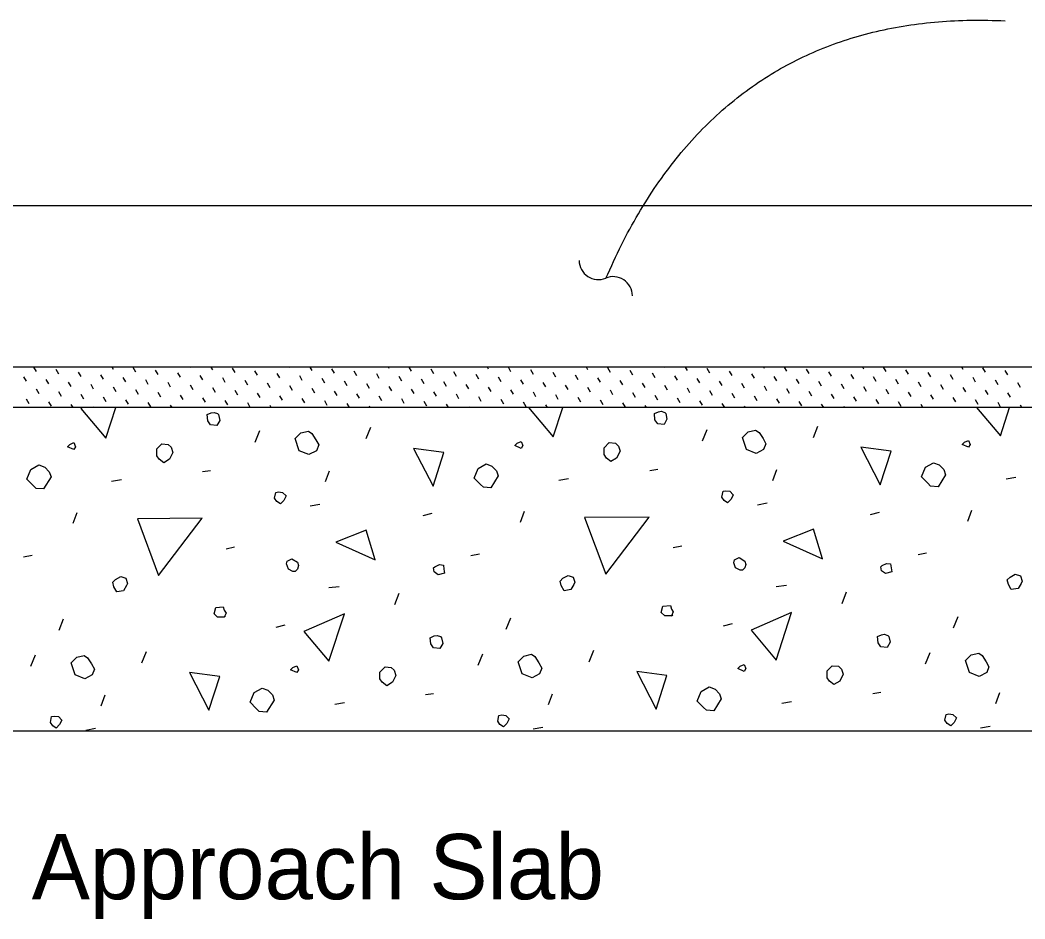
# Model space of a CAD drawing. Extents: x 0 to 40.8, y 1 to 28.
# Drawn here: x 1.979 to 5.085, y 9.449 to 12.227 of the extents above; entities that cross this region are included whole.
import ezdxf

# ---------------------------------------------------------------- set-up
doc = ezdxf.new("R2010")
doc.units = 0
for name, color, linetype in [('Dimension', 7, 'Continuous'), ('Miscellaneous', 7, 'Continuous'), ('TrafBarrierConc', 7, 'Continuous')]:
    doc.layers.add(name, color=color, linetype=linetype)

msp = doc.modelspace()

# ---------------------------------------------------------------- linework, layer by layer
at = {"layer": 'Dimension'}
for centre, start, end in [((3.7662, 11.4849), 180.7649, 292.4921), ((3.8118, 11.3748), 0.7649, 112.4921)]:
    msp.add_arc(centre, 0.0596, start, end, dxfattribs=at)
msp.add_open_spline([(3.7897, 11.4295), (4.1501, 12.2652), (5.0233, 12.2254)], degree=2, dxfattribs=at)
at = {"layer": 'Miscellaneous'}
for p, q in [((2.0293, 11.1415), (2.0218, 11.1545)), ((2.2674, 11.1477), (2.2634, 11.1545)), ((2.3365, 11.1396), (2.3284, 11.1536)), ((2.5054, 11.154), (2.5051, 11.1545)), ((2.5746, 11.1459), (2.5695, 11.1545)), ((2.6437, 11.1378), (2.6356, 11.1517)), ((2.8126, 11.1521), (2.8112, 11.1545)), ((2.8817, 11.144), (2.8756, 11.1545)), ((2.9509, 11.1359), (2.9428, 11.1499)), ((3.1198, 11.1502), (3.1173, 11.1545)), ((3.1889, 11.1421), (3.1817, 11.1545)), ((3.4269, 11.1483), (3.4234, 11.1545)), ((3.4961, 11.1402), (3.488, 11.1542)), ((3.7341, 11.1464), (3.7295, 11.1545)), ((3.8033, 11.1383), (3.7952, 11.1523)), ((3.9722, 11.1527), (3.9711, 11.1545)), ((4.0413, 11.1446), (4.0356, 11.1545)), ((4.1105, 11.1365), (4.1024, 11.1505)), ((4.2793, 11.1508), (4.2772, 11.1545)), ((4.3485, 11.1427), (4.3417, 11.1545)), ((4.5865, 11.1489), (4.5833, 11.1545)), ((4.6557, 11.1408), (4.6478, 11.1545)), ((4.8937, 11.147), (4.8894, 11.1545)), ((4.9629, 11.1389), (4.9548, 11.1529)), ((1.9988, 11.111), (1.9907, 11.125)), ((2.0985, 11.1334), (2.0904, 11.1474)), ((2.1677, 11.1253), (2.1596, 11.1393)), ((2.2368, 11.1172), (2.2287, 11.1312)), ((2.306, 11.1091), (2.2979, 11.1231)), ((2.4057, 11.1315), (2.3976, 11.1455)), ((2.4749, 11.1234), (2.4668, 11.1374)), ((2.544, 11.1153), (2.5359, 11.1293)), ((2.6132, 11.1072), (2.6051, 11.1212)), ((2.7129, 11.1296), (2.7048, 11.1436)), ((2.782, 11.1215), (2.7739, 11.1355)), ((2.8512, 11.1134), (2.8431, 11.1274)), ((2.9204, 11.1053), (2.9123, 11.1193)), ((3.0201, 11.1278), (3.012, 11.1418)), ((3.0892, 11.1197), (3.0811, 11.1337)), ((3.1584, 11.1116), (3.1503, 11.1256)), ((3.2581, 11.134), (3.25, 11.148)), ((3.3273, 11.1259), (3.3192, 11.1399)), ((3.3964, 11.1178), (3.3883, 11.1318)), ((3.4656, 11.1097), (3.4575, 11.1237)), ((3.5653, 11.1321), (3.5572, 11.1461)), ((3.6344, 11.124), (3.6263, 11.138)), ((3.7036, 11.1159), (3.6955, 11.1299)), ((3.7728, 11.1078), (3.7647, 11.1218)), ((3.8725, 11.1302), (3.8644, 11.1442)), ((3.9416, 11.1221), (3.9335, 11.1361)), ((4.0108, 11.114), (4.0027, 11.128)), ((4.08, 11.1059), (4.0719, 11.1199)), ((4.1797, 11.1284), (4.1715, 11.1424)), ((4.2488, 11.1203), (4.2407, 11.1343)), ((4.318, 11.1122), (4.3099, 11.1261)), ((4.4177, 11.1346), (4.4096, 11.1486)), ((4.4868, 11.1265), (4.4787, 11.1405)), ((4.556, 11.1184), (4.5479, 11.1324)), ((4.6252, 11.1103), (4.6171, 11.1243)), ((4.7249, 11.1327), (4.7168, 11.1467)), ((4.794, 11.1246), (4.7859, 11.1386)), ((4.8632, 11.1165), (4.8551, 11.1305)), ((4.9324, 11.1084), (4.9242, 11.1224)), ((5.032, 11.1308), (5.0239, 11.1448)), ((2.068, 11.1029), (2.0599, 11.1169)), ((2.1371, 11.0948), (2.129, 11.1088)), ((2.2063, 11.0867), (2.1982, 11.1007)), ((2.2755, 11.0786), (2.2674, 11.0926)), ((2.3752, 11.101), (2.3671, 11.115)), ((2.4443, 11.0929), (2.4362, 11.1069)), ((2.5135, 11.0848), (2.5054, 11.0988)), ((2.5827, 11.0767), (2.5746, 11.0907)), ((2.6824, 11.0991), (2.6742, 11.1131)), ((2.7515, 11.091), (2.7434, 11.105)), ((2.8207, 11.0829), (2.8126, 11.0969)), ((2.8898, 11.0748), (2.8817, 11.0888)), ((2.9895, 11.0972), (2.9814, 11.1112)), ((3.0587, 11.0891), (3.0506, 11.1031)), ((3.1279, 11.081), (3.1198, 11.095)), ((3.2276, 11.1035), (3.2195, 11.1175)), ((3.2967, 11.0954), (3.2886, 11.1094)), ((3.3659, 11.0873), (3.3578, 11.1013)), ((3.4351, 11.0792), (3.4269, 11.0932)), ((3.5347, 11.1016), (3.5266, 11.1156)), ((3.6039, 11.0935), (3.5958, 11.1075)), ((3.6731, 11.0854), (3.665, 11.0994)), ((3.7422, 11.0773), (3.7341, 11.0913)), ((3.8419, 11.0997), (3.8338, 11.1137)), ((3.9111, 11.0916), (3.903, 11.1056)), ((3.9803, 11.0835), (3.9722, 11.0975)), ((4.0494, 11.0754), (4.0413, 11.0894)), ((4.1491, 11.0978), (4.141, 11.1118)), ((4.2183, 11.0897), (4.2102, 11.1037)), ((4.2874, 11.0816), (4.2793, 11.0956)), ((4.3566, 11.0735), (4.3485, 11.0875)), ((4.3871, 11.1041), (4.379, 11.118)), ((4.4563, 11.096), (4.4482, 11.1099)), ((4.5255, 11.0878), (4.5174, 11.1018)), ((4.5946, 11.0797), (4.5865, 11.0937)), ((4.6943, 11.1022), (4.6862, 11.1162)), ((4.7635, 11.0941), (4.7554, 11.1081)), ((4.8327, 11.086), (4.8246, 11.1)), ((4.9018, 11.0779), (4.8937, 11.0919)), ((5.0015, 11.1003), (4.9934, 11.1143)), ((5.0707, 11.0922), (5.0626, 11.1062)), ((2.0374, 11.0723), (2.0293, 11.0863)), ((2.1066, 11.0642), (2.0985, 11.0782)), ((2.1758, 11.0561), (2.1677, 11.0701)), ((2.2449, 11.048), (2.2368, 11.062)), ((2.3446, 11.0705), (2.3365, 11.0845)), ((2.4138, 11.0624), (2.4057, 11.0764)), ((2.483, 11.0543), (2.4749, 11.0683)), ((2.5521, 11.0462), (2.544, 11.0602)), ((2.6518, 11.0686), (2.6437, 11.0826)), ((2.721, 11.0605), (2.7129, 11.0745)), ((2.7901, 11.0524), (2.782, 11.0664)), ((2.8593, 11.0443), (2.8512, 11.0583)), ((2.959, 11.0667), (2.9509, 11.0807)), ((3.0282, 11.0586), (3.0201, 11.0726)), ((3.0973, 11.0505), (3.0892, 11.0645)), ((3.1665, 11.0424), (3.1584, 11.0564)), ((3.197, 11.0729), (3.1889, 11.0869)), ((3.2662, 11.0648), (3.2581, 11.0788)), ((3.3354, 11.0567), (3.3273, 11.0707)), ((3.4045, 11.0486), (3.3964, 11.0626)), ((3.5042, 11.0711), (3.4961, 11.085)), ((3.5734, 11.063), (3.5653, 11.0769)), ((3.6425, 11.0548), (3.6344, 11.0688)), ((3.7117, 11.0467), (3.7036, 11.0607)), ((3.8114, 11.0692), (3.8033, 11.0832)), ((3.8806, 11.0611), (3.8725, 11.0751)), ((3.9497, 11.053), (3.9416, 11.067)), ((4.0189, 11.0449), (4.0108, 11.0589)), ((4.1186, 11.0673), (4.1105, 11.0813)), ((4.1878, 11.0592), (4.1797, 11.0732)), ((4.2569, 11.0511), (4.2488, 11.0651)), ((4.3261, 11.043), (4.318, 11.057)), ((4.4258, 11.0654), (4.4177, 11.0794)), ((4.4949, 11.0573), (4.4868, 11.0713)), ((4.5641, 11.0492), (4.556, 11.0632)), ((4.6638, 11.0716), (4.6557, 11.0856)), ((4.733, 11.0635), (4.7249, 11.0775)), ((4.8021, 11.0554), (4.794, 11.0694)), ((4.8713, 11.0473), (4.8632, 11.0613)), ((4.971, 11.0698), (4.9629, 11.0838)), ((5.0401, 11.0617), (5.032, 11.0757)), ((2.0069, 11.0418), (1.9988, 11.0558)), ((2.0761, 11.0337), (2.068, 11.0477)), ((2.143, 11.0295), (2.1371, 11.0396)), ((2.2075, 11.0295), (2.2063, 11.0315)), ((2.3141, 11.0399), (2.306, 11.0539)), ((2.3833, 11.0318), (2.3752, 11.0458)), ((2.4491, 11.0295), (2.4443, 11.0377)), ((2.5136, 11.0295), (2.5135, 11.0296)), ((2.6213, 11.0381), (2.6132, 11.0521)), ((2.6905, 11.03), (2.6824, 11.0439)), ((2.7552, 11.0295), (2.7515, 11.0358)), ((2.9285, 11.0362), (2.9204, 11.0502)), ((2.9968, 11.0295), (2.9895, 11.0421)), ((3.0613, 11.0295), (3.0587, 11.034)), ((3.2357, 11.0343), (3.2276, 11.0483)), ((3.3029, 11.0295), (3.2967, 11.0402)), ((3.3674, 11.0295), (3.3659, 11.0321)), ((3.4737, 11.0405), (3.4656, 11.0545)), ((3.5428, 11.0324), (3.5347, 11.0464)), ((3.609, 11.0295), (3.6039, 11.0383)), ((3.6735, 11.0295), (3.6731, 11.0302)), ((3.7809, 11.0386), (3.7728, 11.0526)), ((3.85, 11.0305), (3.8419, 11.0445)), ((3.9151, 11.0295), (3.9111, 11.0364)), ((4.0881, 11.0368), (4.08, 11.0508)), ((4.1567, 11.0295), (4.1491, 11.0427)), ((4.2212, 11.0295), (4.2183, 11.0346)), ((4.3952, 11.0349), (4.3871, 11.0489)), ((4.4628, 11.0295), (4.4563, 11.0408)), ((4.5273, 11.0295), (4.5255, 11.0327)), ((4.6333, 11.0411), (4.6252, 11.0551)), ((4.7024, 11.033), (4.6943, 11.047)), ((4.7689, 11.0295), (4.7635, 11.0389)), ((4.8334, 11.0295), (4.8327, 11.0308)), ((4.9405, 11.0392), (4.9324, 11.0532)), ((5.0096, 11.0311), (5.0015, 11.0451)), ((5.075, 11.0295), (5.0707, 11.037)), ((3.0485, 10.9337), (3.0626, 10.969)), ((4.4309, 10.9372), (4.445, 10.9725)), ((2.7056, 10.923), (2.7197, 10.9584)), ((4.088, 10.9266), (4.1021, 10.9619)), ((2.5677, 10.8347), (2.5429, 10.8311)), ((2.923, 10.8011), (2.9354, 10.8347)), ((3.6743, 10.8099), (3.6442, 10.8046)), ((3.9501, 10.8382), (3.9253, 10.8347)), ((4.3054, 10.8046), (4.3178, 10.8382)), ((5.0567, 10.8134), (5.0266, 10.8081)), ((2.2919, 10.8064), (2.2618, 10.8011)), ((2.9053, 10.7304), (2.8753, 10.7251)), ((4.2877, 10.7339), (4.2577, 10.7286)), ((2.1434, 10.672), (2.1558, 10.7056)), ((3.2518, 10.7021), (3.2235, 10.695)), ((3.5258, 10.6756), (3.5382, 10.7091)), ((4.6342, 10.7056), (4.6059, 10.6985)), ((4.9082, 10.6791), (4.9206, 10.7127)), ((2.6419, 10.5978), (2.6154, 10.5925)), ((4.0243, 10.6013), (3.9978, 10.596)), ((2.0161, 10.573), (1.9896, 10.5677)), ((3.3985, 10.5766), (3.372, 10.5713)), ((4.7809, 10.5801), (4.7544, 10.5748)), ((2.9654, 10.4758), (2.9336, 10.4723)), ((4.3478, 10.4793), (4.316, 10.4758)), ((3.1369, 10.421), (3.151, 10.4564)), ((4.5193, 10.4245), (4.5334, 10.4599)), ((2.0992, 10.3415), (2.1134, 10.3768)), ((3.4816, 10.345), (3.4958, 10.3803)), ((4.864, 10.3485), (4.8781, 10.3839)), ((2.7975, 10.3574), (2.7692, 10.3503)), ((4.1799, 10.3609), (4.1516, 10.3538)), ((2.0126, 10.2301), (2.0267, 10.2654)), ((2.3555, 10.2407), (2.3697, 10.276)), ((3.395, 10.2336), (3.4091, 10.269)), ((3.7379, 10.2442), (3.7521, 10.2796)), ((4.7774, 10.2372), (4.7915, 10.2725)), ((2.23, 10.1081), (2.2424, 10.1417)), ((3.2571, 10.1452), (3.2324, 10.1417)), ((3.6124, 10.1116), (3.6248, 10.1452)), ((4.6395, 10.1488), (4.6147, 10.1452)), ((4.9948, 10.1152), (5.0072, 10.1488)), ((2.9813, 10.1169), (2.9513, 10.1116)), ((4.3637, 10.1205), (4.3337, 10.1152)), ((2.2124, 10.0374), (2.1823, 10.0321)), ((3.5947, 10.0409), (3.5647, 10.0356)), ((4.9771, 10.0445), (4.9471, 10.0392))]:
    msp.add_line(p, q, dxfattribs=at)
for points in [[(2.1714, 11.0295), (2.1664, 11.0273), (2.2442, 10.9354)], [(2.2442, 10.9354), (2.2748, 11.0295)], [(3.5499, 11.0295), (3.6266, 10.939)], [(3.6266, 10.939), (3.656, 11.0295)], [(4.9353, 11.0295), (5.009, 10.9425)], [(5.009, 10.9425), (5.0373, 11.0295)], [(2.596, 10.9902), (2.5871, 10.9743), (2.5677, 10.9761), (2.5588, 10.9885), (2.5571, 11.0079), (2.5694, 11.0132), (2.5783, 11.015), (2.5889, 11.0114), (2.5924, 11.0079), (2.596, 10.9902)], [(3.9784, 10.9938), (3.9695, 10.9779), (3.9501, 10.9796), (3.9412, 10.992), (3.9395, 11.0114), (3.9518, 11.0167), (3.9607, 11.0185), (3.9713, 11.015), (3.9748, 11.0114), (3.9784, 10.9938)], [(2.8947, 10.8965), (2.8717, 10.8842), (2.8417, 10.8965), (2.8293, 10.9337), (2.847, 10.9513), (2.87, 10.9566), (2.8806, 10.9496), (2.8929, 10.9301), (2.9018, 10.9142), (2.8947, 10.8965)], [(4.2771, 10.9001), (4.2541, 10.8877), (4.2241, 10.9001), (4.2117, 10.9372), (4.2294, 10.9549), (4.2524, 10.9602), (4.263, 10.9531), (4.2753, 10.9337), (4.2842, 10.9177), (4.2771, 10.9001)], [(2.1452, 10.9001), (2.1257, 10.9089), (2.1328, 10.916), (2.1452, 10.9213), (2.1505, 10.9089), (2.1452, 10.9001)], [(2.451, 10.8912), (2.4404, 10.87), (2.4227, 10.8594), (2.4086, 10.87), (2.4015, 10.8806), (2.4015, 10.9018), (2.4174, 10.9177), (2.4369, 10.916), (2.4457, 10.9071), (2.451, 10.8912)], [(3.2553, 10.7869), (3.2889, 10.8912), (3.1952, 10.9036), (3.2553, 10.7869)], [(3.5276, 10.9036), (3.5081, 10.9124), (3.5152, 10.9195), (3.5276, 10.9248), (3.5329, 10.9124), (3.5276, 10.9036)], [(3.8334, 10.8948), (3.8228, 10.8736), (3.8051, 10.8629), (3.791, 10.8736), (3.7839, 10.8842), (3.7839, 10.9054), (3.7998, 10.9213), (3.8193, 10.9195), (3.8281, 10.9107), (3.8334, 10.8948)], [(4.6377, 10.7905), (4.6713, 10.8948), (4.5776, 10.9071), (4.6377, 10.7905)], [(4.91, 10.9071), (4.8905, 10.916), (4.8976, 10.923), (4.91, 10.9284), (4.9153, 10.916), (4.91, 10.9071)], [(2.0745, 10.8152), (2.0515, 10.7781), (2.0285, 10.7799), (2.0197, 10.7887), (2.0002, 10.8081), (2.0126, 10.8382), (2.0373, 10.8523), (2.055, 10.8453), (2.0692, 10.8311), (2.0745, 10.8152)], [(3.4569, 10.8188), (3.4339, 10.7816), (3.4109, 10.7834), (3.4021, 10.7922), (3.3826, 10.8117), (3.395, 10.8417), (3.4197, 10.8559), (3.4374, 10.8488), (3.4516, 10.8347), (3.4569, 10.8188)], [(4.8393, 10.8223), (4.8163, 10.7852), (4.7933, 10.7869), (4.7845, 10.7958), (4.765, 10.8152), (4.7774, 10.8453), (4.8021, 10.8594), (4.8198, 10.8523), (4.834, 10.8382), (4.8393, 10.8223)], [(2.7939, 10.7427), (2.7833, 10.7321), (2.7727, 10.7392), (2.7657, 10.7498), (2.7692, 10.7675), (2.778, 10.7693), (2.7904, 10.7675), (2.801, 10.7569), (2.7939, 10.7427)], [(4.1763, 10.7463), (4.1657, 10.7357), (4.1551, 10.7427), (4.1481, 10.7533), (4.1516, 10.771), (4.1604, 10.7728), (4.1728, 10.771), (4.1834, 10.7604), (4.1763, 10.7463)], [(2.4068, 10.5112), (2.5412, 10.6879), (2.3414, 10.6862), (2.4068, 10.5112)], [(3.7892, 10.5147), (3.9236, 10.6915), (3.7238, 10.6897), (3.7892, 10.5147)], [(4.4592, 10.5624), (4.4309, 10.6543), (4.3372, 10.6172), (4.4592, 10.5624)], [(3.0768, 10.5589), (3.0485, 10.6508), (2.9548, 10.6137), (3.0768, 10.5589)], [(2.8293, 10.5235), (2.8222, 10.5235), (2.8081, 10.5306), (2.8028, 10.5465), (2.8046, 10.5554), (2.8187, 10.5624), (2.8364, 10.5518), (2.8399, 10.5412), (2.8364, 10.5306), (2.8293, 10.5235)], [(4.2117, 10.5271), (4.2046, 10.5271), (4.1905, 10.5341), (4.1852, 10.5501), (4.1869, 10.5589), (4.2011, 10.566), (4.2188, 10.5554), (4.2223, 10.5447), (4.2188, 10.5341), (4.2117, 10.5271)], [(3.2907, 10.5182), (3.2712, 10.5129), (3.2589, 10.5218), (3.2571, 10.5341), (3.2606, 10.5377), (3.2748, 10.5447), (3.2872, 10.543), (3.2889, 10.5306), (3.2907, 10.5182)], [(4.6731, 10.5218), (4.6536, 10.5165), (4.6413, 10.5253), (4.6395, 10.5377), (4.643, 10.5412), (4.6572, 10.5483), (4.6695, 10.5465), (4.6713, 10.5341), (4.6731, 10.5218)], [(2.3078, 10.4793), (2.299, 10.4634), (2.2778, 10.4599), (2.2689, 10.4758), (2.2654, 10.4899), (2.2742, 10.4988), (2.2901, 10.5076), (2.306, 10.5023), (2.3113, 10.4864), (2.3078, 10.4793)], [(3.6902, 10.4829), (3.6814, 10.467), (3.6602, 10.4634), (3.6513, 10.4793), (3.6478, 10.4935), (3.6566, 10.5023), (3.6725, 10.5112), (3.6884, 10.5059), (3.6937, 10.4899), (3.6902, 10.4829)], [(5.0726, 10.4864), (5.0638, 10.4705), (5.0425, 10.467), (5.0337, 10.4829), (5.0302, 10.497), (5.039, 10.5059), (5.0549, 10.5147), (5.0708, 10.5094), (5.0761, 10.4935), (5.0726, 10.4864)], [(2.6101, 10.3821), (2.5889, 10.3821), (2.5783, 10.3927), (2.5836, 10.4122), (2.6066, 10.4139), (2.6101, 10.4033), (2.6154, 10.3945), (2.6101, 10.3821), (2.6136, 10.3856)], [(3.9925, 10.3856), (3.9713, 10.3856), (3.9607, 10.3963), (3.966, 10.4157), (3.989, 10.4175), (3.9925, 10.4069), (3.9978, 10.398), (3.9925, 10.3856), (3.996, 10.3892)], [(2.9336, 10.246), (2.9813, 10.3927), (2.8558, 10.3379), (2.9336, 10.246)], [(4.316, 10.2495), (4.3637, 10.3963), (4.2382, 10.3415), (4.316, 10.2495)], [(3.2854, 10.3008), (3.2765, 10.2849), (3.2571, 10.2867), (3.2483, 10.299), (3.2465, 10.3185), (3.2589, 10.3238), (3.2677, 10.3255), (3.2783, 10.322), (3.2819, 10.3185), (3.2854, 10.3008)], [(4.6678, 10.3043), (4.6589, 10.2884), (4.6395, 10.2902), (4.6307, 10.3026), (4.6289, 10.322), (4.6413, 10.3273), (4.6501, 10.3291), (4.6607, 10.3255), (4.6642, 10.322), (4.6678, 10.3043)], [(2.2017, 10.2036), (2.1788, 10.1912), (2.1487, 10.2036), (2.1363, 10.2407), (2.154, 10.2584), (2.177, 10.2637), (2.1876, 10.2566), (2.2, 10.2372), (2.2088, 10.2212), (2.2017, 10.2036)], [(3.5841, 10.2071), (3.5612, 10.1947), (3.5311, 10.2071), (3.5187, 10.2442), (3.5364, 10.2619), (3.5594, 10.2672), (3.57, 10.2601), (3.5824, 10.2407), (3.5912, 10.2248), (3.5841, 10.2071)], [(4.9665, 10.2106), (4.9436, 10.1983), (4.9135, 10.2106), (4.9011, 10.2478), (4.9188, 10.2654), (4.9418, 10.2707), (4.9524, 10.2637), (4.9648, 10.2442), (4.9736, 10.2283), (4.9665, 10.2106)], [(2.8346, 10.2106), (2.8152, 10.2195), (2.8222, 10.2265), (2.8346, 10.2319), (2.8399, 10.2195), (2.8346, 10.2106)], [(3.1404, 10.2018), (3.1298, 10.1806), (3.1121, 10.17), (3.098, 10.1806), (3.0909, 10.1912), (3.0909, 10.2124), (3.1068, 10.2283), (3.1263, 10.2265), (3.1351, 10.2177), (3.1404, 10.2018)], [(4.217, 10.2142), (4.1976, 10.223), (4.2046, 10.2301), (4.217, 10.2354), (4.2223, 10.223), (4.217, 10.2142)], [(4.5228, 10.2053), (4.5122, 10.1841), (4.4945, 10.1735), (4.4804, 10.1841), (4.4733, 10.1947), (4.4733, 10.2159), (4.4892, 10.2319), (4.5087, 10.2301), (4.5175, 10.2212), (4.5228, 10.2053)], [(2.5624, 10.094), (2.596, 10.1983), (2.5023, 10.2106), (2.5624, 10.094)], [(3.9448, 10.0975), (3.9784, 10.2018), (3.8847, 10.2142), (3.9448, 10.0975)], [(2.7639, 10.1258), (2.7409, 10.0887), (2.7179, 10.0904), (2.7091, 10.0993), (2.6896, 10.1187), (2.702, 10.1488), (2.7268, 10.1629), (2.7444, 10.1558), (2.7586, 10.1417), (2.7639, 10.1258)], [(4.1463, 10.1293), (4.1233, 10.0922), (4.1003, 10.094), (4.0915, 10.1028), (4.072, 10.1223), (4.0844, 10.1523), (4.1092, 10.1664), (4.1268, 10.1594), (4.141, 10.1452), (4.1463, 10.1293)], [(2.101, 10.0498), (2.0904, 10.0392), (2.0798, 10.0462), (2.0727, 10.0568), (2.0762, 10.0745), (2.0851, 10.0763), (2.0974, 10.0745), (2.1081, 10.0639), (2.101, 10.0498)], [(3.4834, 10.0533), (3.4728, 10.0427), (3.4622, 10.0498), (3.4551, 10.0604), (3.4586, 10.0781), (3.4675, 10.0798), (3.4798, 10.0781), (3.4904, 10.0675), (3.4834, 10.0533)], [(4.8658, 10.0568), (4.8552, 10.0462), (4.8446, 10.0533), (4.8375, 10.0639), (4.841, 10.0816), (4.8499, 10.0834), (4.8622, 10.0816), (4.8728, 10.071), (4.8658, 10.0568)]]:
    msp.add_lwpolyline(points, dxfattribs=at)
at = {"layer": 'TrafBarrierConc'}
for p, q in [((0.222, 11.6545), (7.9021, 11.6545)), ((7.9021, 11.1545), (0.222, 11.1545)), ((7.9021, 11.0295), (0.222, 11.0295)), ((7.9021, 10.0295), (0.222, 10.0295))]:
    msp.add_line(p, q, dxfattribs=at)

# ---------------------------------------------------------------- texts
at = {"layer": 'Dimension'}
msp.add_text('Approach Slab', height=0.2016, dxfattribs=at).set_placement((2.015, 9.5101))

doc.saveas('drawing.dxf')
